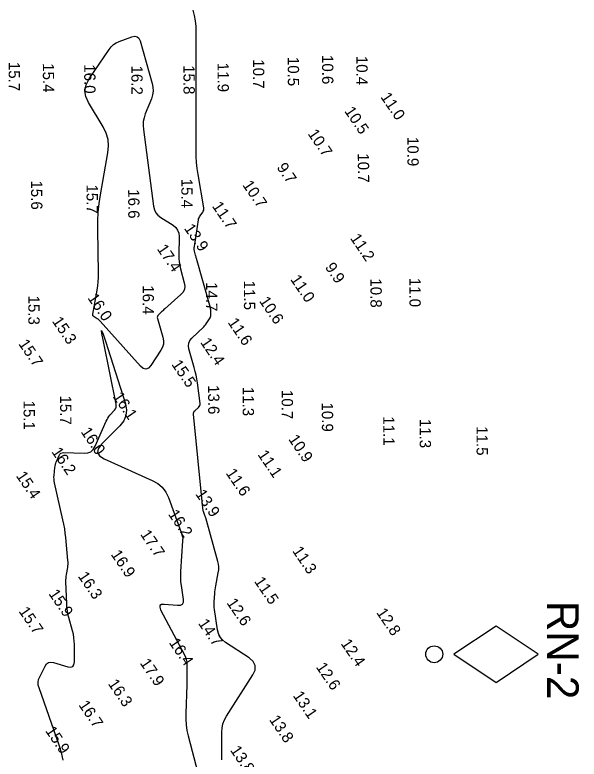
# Model space of a CAD drawing. Extents: x 824616 to 827440, y 158441 to 163197.
# Drawn here: x 826608.3 to 826858.5, y 160568.9 to 160898.9 of the extents above; entities that cross this region are included whole.
import ezdxf

# ---------------------------------------------------------------- set-up
doc = ezdxf.new("R2010")
doc.units = 0
for name, color, linetype in [('V-CHAN-CONT-EL14', 7, 'Continuous'), ('V-CHAN-CONT-EL16', 7, 'Continuous'), ('V-CHAN-NAID', 7, 'Continuous'), ('V-TOPO-SOUN', 7, 'Continuous')]:
    doc.layers.add(name, color=color, linetype=linetype)

msp = doc.modelspace()

# ---------------------------------------------------------------- linework, layer by layer
at = {"layer": 'V-CHAN-CONT-EL14'}
msp.add_lwpolyline([(826700.05, 160568.53), (826700.06, 160569.02), (826700.06, 160569.5), (826700.06, 160569.99), (826699.99, 160580.75), (826700.12, 160582.66), (826700.5, 160584.5), (826701.16, 160586.26), (826702.08, 160587.95), (826713.8, 160606.21), (826714.79, 160608.38), (826714.86, 160610.36), (826713.99, 160612.14), (826712.2, 160613.72), (826701.67, 160620.62), (826700.31, 160621.71), (826699.27, 160623.01), (826698.53, 160624.5), (826698.12, 160626.2), (826696.81, 160635.26), (826696.7, 160636.12), (826696.65, 160636.99), (826696.63, 160637.85), (826696.67, 160638.72), (826696.89, 160642.2), (826696.95, 160643.07), (826697.05, 160643.93), (826697.17, 160644.79), (826697.33, 160645.65), (826698.48, 160651.54), (826698.65, 160652.81), (826698.67, 160654.06), (826698.55, 160655.32), (826698.27, 160656.56), (826692.88, 160675.84), (826692.77, 160676.2), (826692.66, 160676.56), (826692.54, 160676.91), (826692.42, 160677.27), (826691.9, 160678.68), (826691.79, 160679.03), (826691.69, 160679.39), (826691.62, 160679.76), (826691.57, 160680.13), (826687.49, 160721.76), (826687.5, 160722.25), (826687.61, 160722.7), (826687.83, 160723.11), (826688.17, 160723.47), (826689.72, 160724.84), (826690.05, 160725.21), (826690.27, 160725.61), (826690.37, 160726.06), (826690.37, 160726.55), (826689.19, 160735.76), (826688.94, 160737.46), (826688.63, 160739.15), (826688.25, 160740.82), (826687.81, 160742.48), (826685.42, 160750.81), (826685.2, 160752.13), (826685.34, 160753.35), (826685.83, 160754.48), (826686.68, 160755.51), (826691.98, 160760.61), (826692.38, 160761.02), (826692.76, 160761.45), (826693.11, 160761.91), (826693.43, 160762.39), (826694.79, 160764.53), (826695.01, 160764.93), (826695.15, 160765.36), (826695.22, 160765.8), (826695.23, 160766.26), (826695.1, 160768.13), (826695.05, 160768.6), (826694.98, 160769.06), (826694.89, 160769.52), (826694.77, 160769.97), (826688.81, 160790.78), (826688.71, 160791.15), (826688.61, 160791.52), (826688.51, 160791.89), (826688.41, 160792.26), (826687.91, 160794.15), (826687.87, 160794.32), (826687.84, 160794.49), (826687.82, 160794.66), (826687.82, 160794.84), (826687.83, 160795.53), (826687.83, 160795.7), (826687.84, 160795.87), (826687.86, 160796.05), (826687.88, 160796.22), (826689.65, 160807.94), (826689.75, 160808.44), (826689.91, 160808.92), (826690.12, 160809.37), (826690.39, 160809.8), (826691.58, 160811.47), (826691.83, 160811.9), (826691.99, 160812.35), (826692.05, 160812.83), (826692.01, 160813.32), (826689.53, 160828.17), (826689.15, 160830.81), (826688.87, 160833.47), (826688.71, 160836.14), (826688.65, 160838.81), (826688.65, 160857.96), (826688.65, 160861.79), (826688.65, 160865.62), (826688.65, 160869.45), (826688.66, 160873.28), (826688.7, 160891.31), (826688.62, 160893.77), (826688.37, 160896.22), (826687.95, 160898.64), (826687.35, 160901.03)], dxfattribs=at)
at = {"layer": 'V-CHAN-CONT-EL16'}
msp.add_lwpolyline([(826652.04, 160885.68), (826653.23, 160886.47), (826654.56, 160887.07), (826660.16, 160889.15), (826661.44, 160889.42), (826662.47, 160889.21), (826663.25, 160888.5), (826663.78, 160887.31), (826669.14, 160868.52), (826669.49, 160866.79), (826669.55, 160865.08), (826669.31, 160863.38), (826668.79, 160861.7), (826666.1, 160854.99), (826665.54, 160853.3), (826665.21, 160851.58), (826665.11, 160849.83), (826665.23, 160848.05), (826669.77, 160814.01), (826670.13, 160812.5), (826670.77, 160811.17), (826671.7, 160810.02), (826672.92, 160809.06), (826678.38, 160805.57), (826679.57, 160804.61), (826680.42, 160803.45), (826680.92, 160802.11), (826681.07, 160800.59), (826680.99, 160792.47), (826681.02, 160790.88), (826681.17, 160789.31), (826681.41, 160787.75), (826681.77, 160786.21), (826683.4, 160780.05), (826683.61, 160778.57), (826683.42, 160777.21), (826682.83, 160775.98), (826681.84, 160774.86), (826674.71, 160768.49), (826674.35, 160768.17), (826674, 160767.85), (826673.65, 160767.52), (826673.3, 160767.19), (826671.91, 160765.86), (826671.63, 160765.51), (826671.46, 160765.13), (826671.41, 160764.71), (826671.49, 160764.27), (826673.89, 160755.91), (826674.16, 160754.39), (826674.11, 160752.92), (826673.72, 160751.51), (826672.99, 160750.14), (826668.52, 160743.43), (826667.45, 160742.24), (826666.33, 160741.79), (826665.15, 160742.08), (826663.93, 160743.11), (826646.05, 160763.09), (826645.77, 160763.39), (826645.46, 160763.66), (826645.13, 160763.91), (826644.78, 160764.13), (826643.35, 160764.98), (826643.05, 160765.22), (826642.85, 160765.5), (826642.76, 160765.84), (826642.79, 160766.22), (826644.73, 160776.76), (826645.03, 160778.66), (826645.24, 160780.57), (826645.35, 160782.48), (826645.36, 160784.4), (826645, 160803.75), (826645.03, 160807.61), (826645.24, 160811.45), (826645.63, 160815.28), (826646.22, 160819.1), (826649.54, 160837.7), (826649.82, 160840.74), (826649.56, 160843.67), (826648.75, 160846.5), (826647.4, 160849.24), (826640.91, 160859.96), (826639.71, 160862.63), (826639.35, 160865.27), (826639.85, 160867.9), (826641.19, 160870.5), (826650.08, 160883.57), (826650.99, 160884.71)], close=True, dxfattribs=at)
msp.add_lwpolyline([(826629.7, 160568.45), (826628.87, 160571.75), (826628.66, 160572.57), (826628.42, 160573.38), (826628.17, 160574.19), (826627.9, 160574.99), (826618.96, 160600.46), (826618.65, 160601.71), (826618.59, 160602.94), (826618.8, 160604.15), (826619.26, 160605.35), (826621.62, 160610.12), (826622.29, 160611.11), (826623.14, 160611.71), (826624.16, 160611.91), (826625.34, 160611.73), (826631.67, 160609.8), (826632.96, 160609.6), (826633.89, 160609.9), (826634.45, 160610.7), (826634.64, 160612), (826634.66, 160619.65), (826634.61, 160621.19), (826634.46, 160622.72), (826634.2, 160624.23), (826633.84, 160625.72), (826632.17, 160631.68), (826631.8, 160633.18), (826631.52, 160634.69), (826631.33, 160636.21), (826631.23, 160637.75), (826630.91, 160647.56), (826630.9, 160648.34), (826630.93, 160649.13), (826631.01, 160649.91), (826631.12, 160650.68), (826631.67, 160653.79), (826631.78, 160654.57), (826631.83, 160655.34), (826631.84, 160656.13), (826631.79, 160656.91), (826630.83, 160667.13), (826630.61, 160669.09), (826630.34, 160671.04), (826629.99, 160672.98), (826629.59, 160674.91), (826625.85, 160691.39), (826625.7, 160692.19), (826625.62, 160693), (826625.6, 160693.82), (826625.65, 160694.63), (826626.01, 160698.11), (826626.11, 160698.82), (826626.27, 160699.52), (826626.47, 160700.2), (826626.73, 160700.87), (826627.88, 160703.53), (826628.22, 160704.1), (826628.66, 160704.51), (826629.22, 160704.74), (826629.89, 160704.8), (826638.96, 160704.49), (826640.59, 160704.64), (826641.95, 160705.2), (826643.04, 160706.18), (826643.88, 160707.58), (826648.78, 160718.75), (826649.11, 160719.44), (826649.49, 160720.1), (826649.93, 160720.72), (826650.41, 160721.32), (826652.45, 160723.63), (826652.87, 160724.23), (826653.13, 160724.87), (826653.23, 160725.56), (826653.16, 160726.29), (826647.49, 160753.98), (826646.81, 160757.64), (826646.74, 160758.91), (826647.3, 160757.77), (826648.48, 160754.23), (826657.25, 160726.38), (826657.75, 160723.69), (826657.53, 160721.18), (826656.56, 160718.85), (826654.86, 160716.71), (826646.6, 160708.48), (826645.13, 160706.53), (826644.83, 160704.81), (826645.72, 160703.29), (826647.8, 160702), (826669.2, 160692.48), (826671.59, 160691.14), (826673.58, 160689.41), (826675.17, 160687.31), (826676.34, 160684.82), (826682, 160669.29), (826682.09, 160669.04), (826682.17, 160668.78), (826682.25, 160668.53), (826682.32, 160668.28), (826682.69, 160666.97), (826682.71, 160666.86), (826682.72, 160666.74), (826682.72, 160666.63), (826682.71, 160666.51), (826682.62, 160666.05), (826682.6, 160665.94), (826682.58, 160665.82), (826682.57, 160665.7), (826682.56, 160665.59), (826681.7, 160652.01), (826681.65, 160650.48), (826681.67, 160648.94), (826681.77, 160647.41), (826681.95, 160645.88), (826682.86, 160639.63), (826682.86, 160638.37), (826682.44, 160637.5), (826681.6, 160637.03), (826680.34, 160636.95), (826674.46, 160637.42), (826673.26, 160637.36), (826672.6, 160636.95), (826672.48, 160636.18), (826672.9, 160635.05), (826683.46, 160615.05), (826683.92, 160614.03), (826684.25, 160612.99), (826684.46, 160611.91), (826684.53, 160610.8), (826684.56, 160606.29), (826684.56, 160605.16), (826684.55, 160604.04), (826684.52, 160602.91), (826684.49, 160601.78), (826684.03, 160589.04), (826684.03, 160586.55), (826684.2, 160584.08), (826684.56, 160581.62), (826685.09, 160579.19), (826689.32, 160562.78)], dxfattribs=at)
at = {"layer": 'V-CHAN-NAID'}
msp.add_lwpolyline([(826802.97, 160615.36), (826821.67, 160602.89), (826840.37, 160615.36), (826821.67, 160627.83)], close=True, dxfattribs=at)
msp.add_circle((826794.24, 160615.36), 3.74, dxfattribs=at)

# ---------------------------------------------------------------- texts
msp.add_text('RN-2', height=14, rotation=270, dxfattribs=at).set_placement((826844.28, 160639.07))
at = {"layer": 'V-TOPO-SOUN'}
for s, rotation, p in [('10.6 ', 270.2, (826744.47, 160881.08)), ('10.4 ', 270.2, (826759.68, 160880.71)), ('15.7 ', 270.2, (826605.49, 160878.04)), ('15.4 ', 270.2, (826620.65, 160877.45)), ('11.9 ', 270.2, (826698.13, 160877.66)), ('10.7 ', 270.2, (826713.85, 160879.17)), ('10.5 ', 270.2, (826729.26, 160880.26)), ('16.0 ', 270.2, (826638.99, 160876.98)), ('16.2 ', 270.2, (826659.91, 160876.43)), ('15.8 ', 270.2, (826683, 160876.59)), ('11.0 ', 304.2, (826770.23, 160862.47)), ('10.5 ', 304.2, (826754.19, 160856.22)), ('10.7 ', 304.2, (826737.96, 160846.18)), ('10.9 ', 270.2, (826782.3, 160844.76)), ('10.7 ', 270.2, (826760.34, 160837.48)), ('9.7', 304.2, (826724.19, 160831.24)), ('15.6 ', 270.2, (826615.43, 160825.47)), ('15.4 ', 270.2, (826682.06, 160826.23)), ('10.7 ', 304.2, (826709, 160823.47)), ('15.7 ', 270.2, (826640.04, 160823.69)), ('16.6 ', 270.2, (826658.49, 160821.57)), ('11.7 ', 304.2, (826695.52, 160814.07)), ('13.9 ', 304.2, (826683.1, 160804.23)), ('11.2 ', 304.2, (826756.76, 160799.87)), ('17.4 ', 304.2, (826671.07, 160795.12)), ('9.9', 304.2, (826745.6, 160786.99)), ('11.0 ', 304.2, (826730.21, 160781.63)), ('10.8 ', 270.2, (826765.93, 160782.04)), ('11.0 ', 270.2, (826783.19, 160782.31)), ('16.4 ', 270.2, (826664.91, 160778.98)), ('14.7 ', 270.2, (826693.03, 160780.39)), ('11.5 ', 270.2, (826709.8, 160781.02)), ('16.0 ', 304.2, (826640.32, 160773.35)), ('15.3 ', 270.2, (826614.2, 160774.43)), ('10.6 ', 304.2, (826716.41, 160772)), ('15.3 ', 304.2, (826624.56, 160763.05)), ('11.6 ', 304.2, (826702.48, 160762.51)), ('15.7 ', 304.2, (826609.64, 160753.02)), ('12.4 ', 304.2, (826690.28, 160753.7)), ('15.5 ', 304.2, (826677.52, 160743.92)), ('16.1 ', 304.2, (826651.46, 160729.63)), ('13.6 ', 270.2, (826693.94, 160734.73)), ('11.3 ', 270.2, (826709.26, 160733.96)), ('10.7 ', 270.2, (826726.57, 160732.57)), ('15.7 ', 270.2, (826628.3, 160730.1)), ('15.1 ', 270.2, (826612.1, 160727.87)), ('10.9 ', 270.2, (826744.37, 160727)), ('11.1 ', 270.2, (826771.6, 160720.86)), ('11.3 ', 270.2, (826787.76, 160719.76)), ('16.0 ', 304.2, (826637.29, 160714.01)), ('11.5 ', 270.2, (826812.98, 160716.48)), ('10.9 ', 304.2, (826729.35, 160710.76)), ('16.2 ', 304.2, (826624.33, 160705.14)), ('11.1 ', 304.2, (826715.73, 160703.9)), ('15.4 ', 304.2, (826608.57, 160694.48)), ('11.6 ', 304.2, (826701.59, 160695.73)), ('13.9 ', 304.2, (826688.14, 160686.43)), ('16.2 ', 304.2, (826676.03, 160677.49)), ('17.7 ', 304.2, (826663.65, 160668.57)), ('11.3 ', 304.2, (826731.09, 160661.21)), ('16.9 ', 304.2, (826650.62, 160659.64)), ('16.3 ', 304.2, (826636.01, 160649.99)), ('11.5 ', 304.2, (826714.19, 160647.72)), ('15.9 ', 304.2, (826623.03, 160642.19)), ('12.6 ', 304.2, (826701.96, 160638.19)), ('15.7 ', 304.2, (826609.76, 160634.44)), ('12.8 ', 304.2, (826768.36, 160633.84)), ('14.7 ', 304.2, (826689.34, 160629.08)), ('16.4 ', 304.2, (826676.39, 160620.52)), ('12.4 ', 304.2, (826752.59, 160620.14)), ('17.9 ', 304.2, (826663.51, 160611.48)), ('12.6 ', 304.2, (826741.6, 160609.71)), ('16.3 ', 304.2, (826649.35, 160602.33)), ('13.1 ', 304.2, (826731.39, 160597.02)), ('16.7 ', 304.2, (826636.32, 160592.9)), ('13.8 ', 304.2, (826720.84, 160586.37)), ('15.9 ', 304.2, (826621.55, 160581.44)), ('13.8 ', 304.2, (826703.54, 160572.83))]:
    msp.add_text(s, height=5, rotation=rotation, dxfattribs=at).set_placement(p)

doc.saveas('drawing.dxf')
